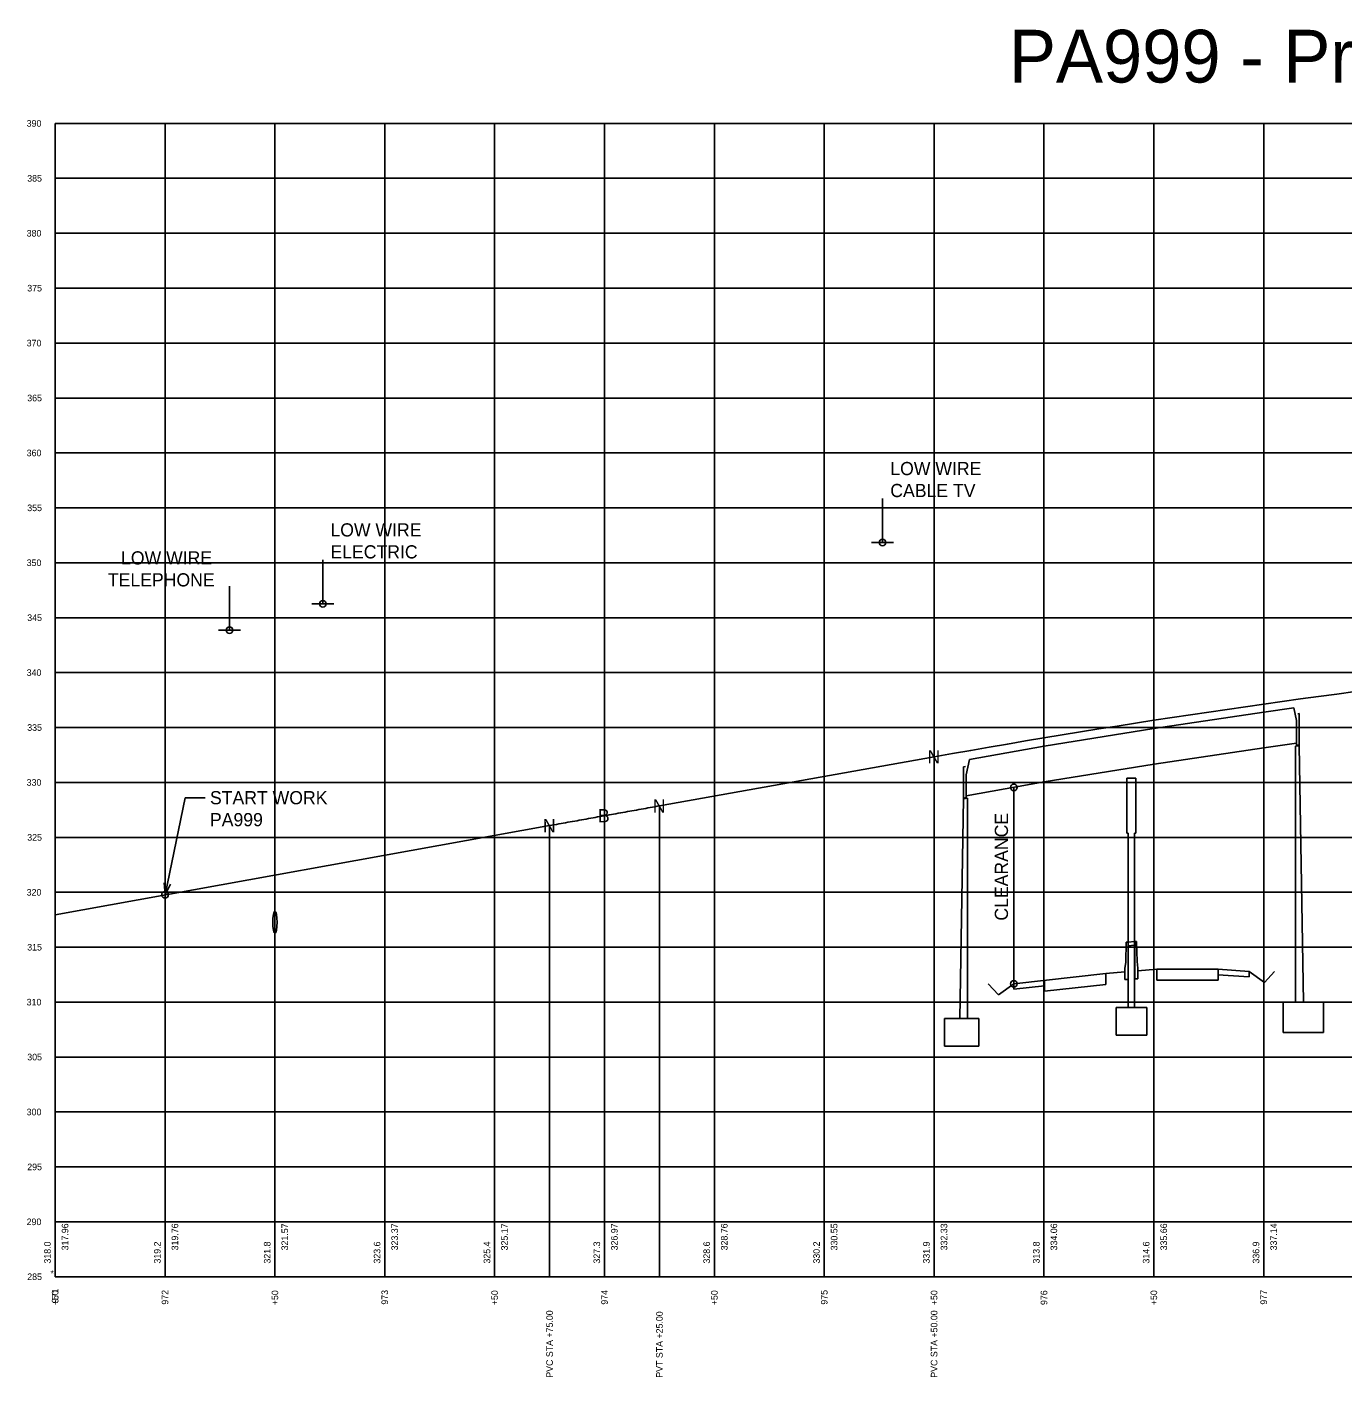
# Model space of a CAD drawing. Extents: x 4987 to 6162, y 4954 to 5569.
# Drawn here: x 4987 to 5586, y 4954 to 5569 of the extents above; entities that cross this region are included whole.
import ezdxf

# ---------------------------------------------------------------- set-up
doc = ezdxf.new("R2010")
doc.units = 0
for name, color, linetype in [('1', 7, 'Continuous'), ('15', 7, 'Continuous'), ('18', 7, 'Continuous'), ('20', 7, 'Continuous'), ('21', 7, 'Continuous'), ('3', 7, 'Continuous'), ('33', 7, 'Continuous'), ('39', 7, 'Continuous'), ('61', 7, 'Continuous'), ('63', 7, 'Continuous')]:
    doc.layers.add(name, color=color, linetype=linetype)

msp = doc.modelspace()

# ---------------------------------------------------------------- linework, layer by layer
at = {"layer": '1'}
for p, q in [((5000, 5000), (6150, 5000)), ((5000, 5000), (5000, 5000)), ((5050, 5000), (5050, 5000)), ((5100, 5000), (5100, 5000)), ((5150, 5000), (5150, 5000)), ((5200, 5000), (5200, 5000)), ((5250, 5000), (5250, 5000)), ((5300, 5000), (5300, 5000)), ((5350, 5000), (5350, 5000)), ((5400, 5000), (5400, 5000)), ((5450, 5000), (5450, 5000)), ((5500, 5000), (5500, 5000)), ((5550, 5000), (5550, 5000))]:
    msp.add_line(p, q, dxfattribs=at)
for points in [[(5400, 5236.66), (5400, 5000), (5400, 5000), (5400, 5000)], [(5275, 5214.32), (5275, 5000), (5275, 5000), (5275, 5000)], [(5225, 5205.35), (5225, 5000), (5225, 5000), (5225, 5000)], [(5000, 5000), (5000, 5035)], [(5000, 5000), (5000, 5035)], [(5000, 5000), (5000, 5035)], [(5050, 5000), (5050, 5035)], [(5050, 5000), (5050, 5035)], [(5050, 5000), (5050, 5035)], [(5100, 5000), (5100, 5035)], [(5100, 5000), (5100, 5035)], [(5100, 5000), (5100, 5035)], [(5150, 5000), (5150, 5035)], [(5150, 5000), (5150, 5035)], [(5150, 5000), (5150, 5035)], [(5200, 5000), (5200, 5035)], [(5200, 5000), (5200, 5035)], [(5200, 5000), (5200, 5035)], [(5225, 5000), (5225, 5035)], [(5250, 5000), (5250, 5035)], [(5250, 5000), (5250, 5035)], [(5250, 5000), (5250, 5035)], [(5275, 5000), (5275, 5035)], [(5300, 5000), (5300, 5035)], [(5300, 5000), (5300, 5035)], [(5300, 5000), (5300, 5035)], [(5350, 5000), (5350, 5035)], [(5350, 5000), (5350, 5035)], [(5350, 5000), (5350, 5035)], [(5400, 5000), (5400, 5035)], [(5400, 5000), (5400, 5035)], [(5400, 5000), (5400, 5035)], [(5450, 5000), (5450, 5035)], [(5450, 5000), (5450, 5035)], [(5450, 5000), (5450, 5035)], [(5500, 5000), (5500, 5035)], [(5500, 5000), (5500, 5035)], [(5500, 5000), (5500, 5035)], [(5550, 5000), (5550, 5035)], [(5550, 5000), (5550, 5035)], [(5550, 5000), (5550, 5035)]]:
    msp.add_lwpolyline(points, dxfattribs=at)
at = {"layer": '15'}
for p, q in [((5376.56, 5334.23), (5376.56, 5354.23)), ((5371.56, 5334.23), (5381.56, 5334.23)), ((5121.78, 5306.31), (5121.78, 5326.31)), ((5079.36, 5294.34), (5079.36, 5314.34)), ((5116.78, 5306.31), (5126.78, 5306.31)), ((5074.36, 5294.34), (5084.36, 5294.34))]:
    msp.add_line(p, q, dxfattribs=at)
for centre in [(5376.56, 5334.23), (5121.78, 5306.31), (5079.36, 5294.34), (5436.25, 5222.77), (5050, 5173.82), (5436.25, 5133.35)]:
    msp.add_circle(centre, 1.5, dxfattribs=at)
at = {"layer": '18'}
for p in [(5050, 5173.82), (5068.2, 5218.07)]:
    msp.add_line(p, (5059.2, 5218.07), dxfattribs=at)
msp.add_lwpolyline([(5052.53, 5178.63), (5050, 5173.82), (5049.6, 5179.24)], dxfattribs=at)
msp.add_ellipse((5100, 5161.35), major_axis=(0, 5), ratio=0.2, dxfattribs=at)
at = {"layer": '20'}
msp.add_line((5436.25, 5133.35), (5436.25, 5222.77), dxfattribs=at)
at = {"layer": '21'}
for p, q in [((5500.02, 5249.55), (5550.02, 5257.05)), ((5550.02, 5257.05), (5563.75, 5258.92)), ((5564.9, 5253.14), (5563.75, 5258.92)), ((5565.5, 5256.22), (5566.15, 5256.33)), ((5566.15, 5241.74), (5566.15, 5256.33)), ((5450.02, 5241.45), (5500.02, 5249.55)), ((5564.9, 5241.57), (5564.9, 5253.14)), ((5550.11, 5240.81), (5564.9, 5242.82)), ((5564.9, 5241.99), (5566.15, 5242.16)), ((5416.06, 5235.47), (5450.03, 5241.45)), ((5500.12, 5233.31), (5550.12, 5240.81)), ((5564.41, 5241.5), (5566.15, 5241.74)), ((5564.41, 5241.5), (5564.41, 5125)), ((5566.15, 5241.74), (5568.11, 5125)), ((5413.41, 5232.09), (5414.28, 5232.23)), ((5413.41, 5217.5), (5413.41, 5232.09)), ((5414.66, 5228.45), (5416.06, 5235.47)), ((5450.13, 5225.21), (5500.13, 5233.31)), ((5414.66, 5217.72), (5414.66, 5228.45)), ((5414.66, 5218.97), (5450.14, 5225.21)), ((5487.75, 5201.94), (5487.75, 5226.94)), ((5491.82, 5226.94), (5487.75, 5226.94)), ((5491.82, 5201.94), (5491.82, 5226.94)), ((5413.41, 5217.5), (5411.73, 5117.5)), ((5413.41, 5217.91), (5414.66, 5218.13)), ((5413.41, 5217.5), (5415.15, 5217.8)), ((5415.15, 5217.8), (5415.15, 5117.5)), ((5488.33, 5201.94), (5487.75, 5201.94)), ((5488.33, 5122.5), (5488.33, 5201.94)), ((5491.82, 5201.94), (5491.24, 5201.94)), ((5491.24, 5122.5), (5491.24, 5201.94)), ((5487.22, 5143.22), (5487.42, 5152.32)), ((5488.25, 5152.32), (5487.42, 5152.32)), ((5488.25, 5152.32), (5488.25, 5135.35)), ((5488.33, 5152.32), (5491.24, 5152.57)), ((5488.33, 5150.67), (5491.24, 5150.92)), ((5491.32, 5135.61), (5491.32, 5152.57)), ((5491.32, 5152.57), (5492.15, 5152.57)), ((5492.35, 5143.47), (5492.15, 5152.57)), ((5492.35, 5143.47), (5492.76, 5140.52)), ((5478.14, 5138.05), (5436.25, 5133.35)), ((5478.14, 5138.05), (5486.81, 5138.78)), ((5478.14, 5138.05), (5478.17, 5133.05)), ((5487.22, 5143.22), (5486.81, 5140.27)), ((5486.81, 5135.35), (5486.81, 5140.27)), ((5492.76, 5135.61), (5492.76, 5140.52)), ((5492.76, 5139.27), (5501.42, 5140)), ((5501.42, 5140), (5501.42, 5135)), ((5529.2, 5140), (5501.42, 5140)), ((5529.19, 5137.5), (5543.31, 5136.5)), ((5529.2, 5135), (5529.2, 5140)), ((5529.2, 5140), (5543.32, 5139)), ((5543.32, 5139), (5543.31, 5136.5)), ((5550.3, 5134), (5543.32, 5139)), ((5554.95, 5139), (5550.3, 5134)), ((5424.61, 5133.35), (5429.27, 5128.35)), ((5429.27, 5128.35), (5436.25, 5133.35)), ((5436.26, 5130.85), (5436.25, 5133.35)), ((5450.29, 5132.42), (5436.26, 5130.85)), ((5450.3, 5129.93), (5450.28, 5134.92)), ((5478.17, 5133.05), (5450.3, 5129.93)), ((5488.25, 5135.35), (5486.81, 5135.35)), ((5491.32, 5135.61), (5492.76, 5135.61)), ((5529.2, 5135), (5501.42, 5135)), ((5482.8, 5110), (5482.8, 5122.5)), ((5482.8, 5122.5), (5496.76, 5122.5)), ((5496.76, 5110), (5496.76, 5122.5)), ((5558.88, 5111.25), (5558.88, 5125)), ((5577.21, 5125), (5558.88, 5125)), ((5577.21, 5111.25), (5577.21, 5125)), ((5404.68, 5105), (5404.68, 5117.5)), ((5404.68, 5117.5), (5420.39, 5117.5)), ((5420.39, 5105), (5420.39, 5117.5)), ((5482.8, 5110), (5496.76, 5110)), ((5577.21, 5111.25), (5558.88, 5111.25)), ((5404.68, 5105), (5420.39, 5105))]:
    msp.add_line(p, q, dxfattribs=at)
at = {"layer": '39'}
for p, q in [((5275, 5214.32), (5400, 5236.66)), ((5000, 5164.81), (5225, 5205.35))]:
    msp.add_line(p, q, dxfattribs=at)
for points in [[(5400, 5236.66), (5408.33, 5238.14), (5416.67, 5239.6), (5425, 5241.05), (5433.33, 5242.48), (5441.67, 5243.89), (5450, 5245.29), (5458.33, 5246.66), (5466.67, 5248.02), (5475, 5249.37), (5483.33, 5250.69), (5491.67, 5252), (5500, 5253.29), (5508.33, 5254.57), (5516.67, 5255.82), (5525, 5257.06), (5533.33, 5258.28), (5541.67, 5259.49), (5550, 5260.68), (5558.33, 5261.85), (5566.67, 5263), (5575, 5264.14), (5583.33, 5265.26), (5591.67, 5266.36)], [(5225, 5205.35), (5226.04, 5205.54), (5227.08, 5205.73), (5228.12, 5205.91), (5229.17, 5206.1), (5230.21, 5206.29), (5231.25, 5206.48), (5232.29, 5206.66), (5233.33, 5206.85), (5234.37, 5207.04), (5235.42, 5207.23), (5236.46, 5207.41), (5237.5, 5207.6), (5238.54, 5207.79), (5239.58, 5207.97), (5240.62, 5208.16), (5241.67, 5208.35), (5242.71, 5208.54), (5243.75, 5208.72), (5244.79, 5208.91), (5245.83, 5209.1), (5246.87, 5209.28), (5247.92, 5209.47), (5248.96, 5209.66), (5251.04, 5210.03), (5252.08, 5210.22), (5253.12, 5210.41), (5254.17, 5210.59), (5255.21, 5210.78), (5256.25, 5210.97), (5257.29, 5211.15), (5258.33, 5211.34), (5259.37, 5211.53), (5260.42, 5211.71), (5261.46, 5211.9), (5262.5, 5212.09), (5263.54, 5212.27), (5264.58, 5212.46), (5265.62, 5212.65), (5266.67, 5212.83), (5267.71, 5213.02), (5268.75, 5213.21), (5269.79, 5213.39), (5270.83, 5213.58), (5271.87, 5213.76), (5272.92, 5213.95), (5273.96, 5214.14), (5275, 5214.32)]]:
    msp.add_lwpolyline(points, dxfattribs=at)
at = {"layer": '63'}
for p, q in [((5000, 5000), (5000, 5525)), ((5000, 5525), (5000, 5525)), ((5000, 5525), (5000, 5525)), ((5000, 5525), (6150, 5525)), ((5000, 5525), (6150, 5525)), ((5050, 5000), (5050, 5525)), ((5100, 5000), (5100, 5525)), ((5150, 5000), (5150, 5525)), ((5200, 5000), (5200, 5525)), ((5250, 5000), (5250, 5525)), ((5300, 5000), (5300, 5525)), ((5350, 5000), (5350, 5525)), ((5400, 5000), (5400, 5525)), ((5450, 5000), (5450, 5525)), ((5500, 5000), (5500, 5525)), ((5550, 5000), (5550, 5525)), ((5000, 5500), (5000, 5500)), ((5000, 5500), (6150, 5500)), ((5000, 5475), (5000, 5475)), ((5000, 5475), (6150, 5475)), ((5000, 5450), (5000, 5450)), ((5000, 5450), (6150, 5450)), ((5000, 5425), (5000, 5425)), ((5000, 5425), (6150, 5425)), ((5000, 5400), (5000, 5400)), ((5000, 5400), (6150, 5400)), ((5000, 5375), (5000, 5375)), ((5000, 5375), (6150, 5375)), ((5000, 5350), (5000, 5350)), ((5000, 5350), (6150, 5350)), ((5000, 5325), (5000, 5325)), ((5000, 5325), (6150, 5325)), ((5000, 5300), (5000, 5300)), ((5000, 5300), (6150, 5300)), ((5000, 5275), (5000, 5275)), ((5000, 5275), (6150, 5275)), ((5000, 5250), (5000, 5250)), ((5000, 5250), (6150, 5250)), ((5000, 5225), (5000, 5225)), ((5000, 5225), (6150, 5225)), ((5000, 5200), (5000, 5200)), ((5000, 5200), (6150, 5200)), ((5000, 5175), (5000, 5175)), ((5000, 5175), (6150, 5175)), ((5000, 5150), (5000, 5150)), ((5000, 5150), (6150, 5150)), ((5000, 5125), (5000, 5125)), ((5000, 5125), (6150, 5125)), ((5000, 5100), (5000, 5100)), ((5000, 5100), (6150, 5100)), ((5000, 5075), (5000, 5075)), ((5000, 5075), (6150, 5075)), ((5000, 5050), (5000, 5050)), ((5000, 5050), (6150, 5050)), ((5000, 5025), (5000, 5025)), ((5000, 5025), (6150, 5025)), ((5000, 5000), (5000, 5000))]:
    msp.add_line(p, q, dxfattribs=at)

# ---------------------------------------------------------------- texts
at = {"layer": '1'}
msp.add_text('PA999 - Proposed', height=24, dxfattribs=at).set_placement((5434.05, 5543.6))
at = {"layer": '15'}
for s, p in [('LOW WIRE', (5380.06, 5364.89)), ('CABLE TV', (5380.06, 5354.89)), ('LOW WIRE', (5125.27, 5336.97)), ('LOW WIRE', (5029.99, 5324.23)), ('ELECTRIC', (5125.27, 5326.97)), ('TELEPHONE', (5023.99, 5314.23))]:
    msp.add_text(s, height=6, dxfattribs=at).set_placement(p)
msp.add_text('CLEARANCE', height=6, rotation=90, dxfattribs=at).set_placement((5433.63, 5162.1))
at = {"layer": '18'}
for s, p in [('START WORK', (5070.45, 5215.07)), ('PA999', (5070.45, 5205.07))]:
    msp.add_text(s, height=6, dxfattribs=at).set_placement(p)
at = {"layer": '3'}
for s, p in [('318.0', (4998, 5006)), ('319.2', (5048, 5006)), ('321.8', (5098, 5006)), ('323.6', (5148, 5006)), ('325.4', (5198, 5006)), ('327.3', (5248, 5006)), ('328.6', (5298, 5006)), ('330.2', (5348, 5006)), ('331.9', (5398, 5006)), ('313.8', (5448, 5006)), ('314.6', (5498, 5006)), ('336.9', (5548, 5006))]:
    msp.add_text(s, height=3, rotation=90, dxfattribs=at).set_placement(p)
at = {"layer": '33'}
for s, p in [('317.96', (5006, 5012)), ('319.76', (5056, 5012)), ('321.57', (5106, 5012)), ('323.37', (5156, 5012)), ('325.17', (5206, 5012)), ('326.97', (5256, 5012)), ('328.76', (5306, 5012)), ('330.55', (5356, 5012)), ('332.33', (5406, 5012)), ('334.06', (5456, 5012)), ('335.66', (5506, 5012)), ('337.14', (5556, 5012)), ('971', (5001.5, 4987.98)), ('+50', (5001.5, 4987.04)), ('972', (5051.5, 4987.3)), ('+50', (5101.5, 4987.04)), ('973', (5151.5, 4987.3)), ('+50', (5201.5, 4987.04)), ('974', (5251.5, 4987.3)), ('+50', (5301.5, 4987.04)), ('975', (5351.5, 4987.3)), ('+50', (5401.5, 4987.04)), ('976', (5451.5, 4987.13)), ('+50', (5501.5, 4987.04)), ('977', (5551.5, 4987.3)), ('PVC STA +75.00', (5226.5, 4954.04)), ('PVT STA +25.00', (5276.5, 4954.04)), ('PVC STA +50.00', (5401.5, 4954.04))]:
    msp.add_text(s, height=3, rotation=90, dxfattribs=at).set_placement(p)
at = {"layer": '61'}
for s, p in [('N', (5397, 5233.66)), ('N', (5272, 5211.32)), ('B', (5247, 5206.86)), ('N', (5222, 5202.35))]:
    msp.add_text(s, height=6, dxfattribs=at).set_placement(p)
at = {"layer": '63'}
for s, p in [('390', (4987.04, 5523.5)), ('390', (4987.04, 5523.5)), ('385', (4987.3, 5498.5)), ('380', (4987.04, 5473.5)), ('375', (4987.3, 5448.5)), ('370', (4987.04, 5423.5)), ('365', (4987.3, 5398.5)), ('360', (4987.04, 5373.5)), ('355', (4987.3, 5348.5)), ('350', (4987.04, 5323.5)), ('345', (4987.3, 5298.5)), ('340', (4987.04, 5273.5)), ('335', (4987.3, 5248.5)), ('330', (4987.04, 5223.5)), ('325', (4987.3, 5198.5)), ('320', (4987.04, 5173.5)), ('315', (4987.3, 5148.5)), ('310', (4987.04, 5123.5)), ('305', (4987.3, 5098.5)), ('300', (4987.04, 5073.5)), ('295', (4987.3, 5048.5)), ('290', (4987.04, 5023.5)), ('*', (4997.84, 5000)), ('*', (4997.84, 5000)), ('*', (4997.84, 5000)), ('285', (4987.3, 4998.5))]:
    msp.add_text(s, height=3, dxfattribs=at).set_placement(p)

doc.saveas('drawing.dxf')
